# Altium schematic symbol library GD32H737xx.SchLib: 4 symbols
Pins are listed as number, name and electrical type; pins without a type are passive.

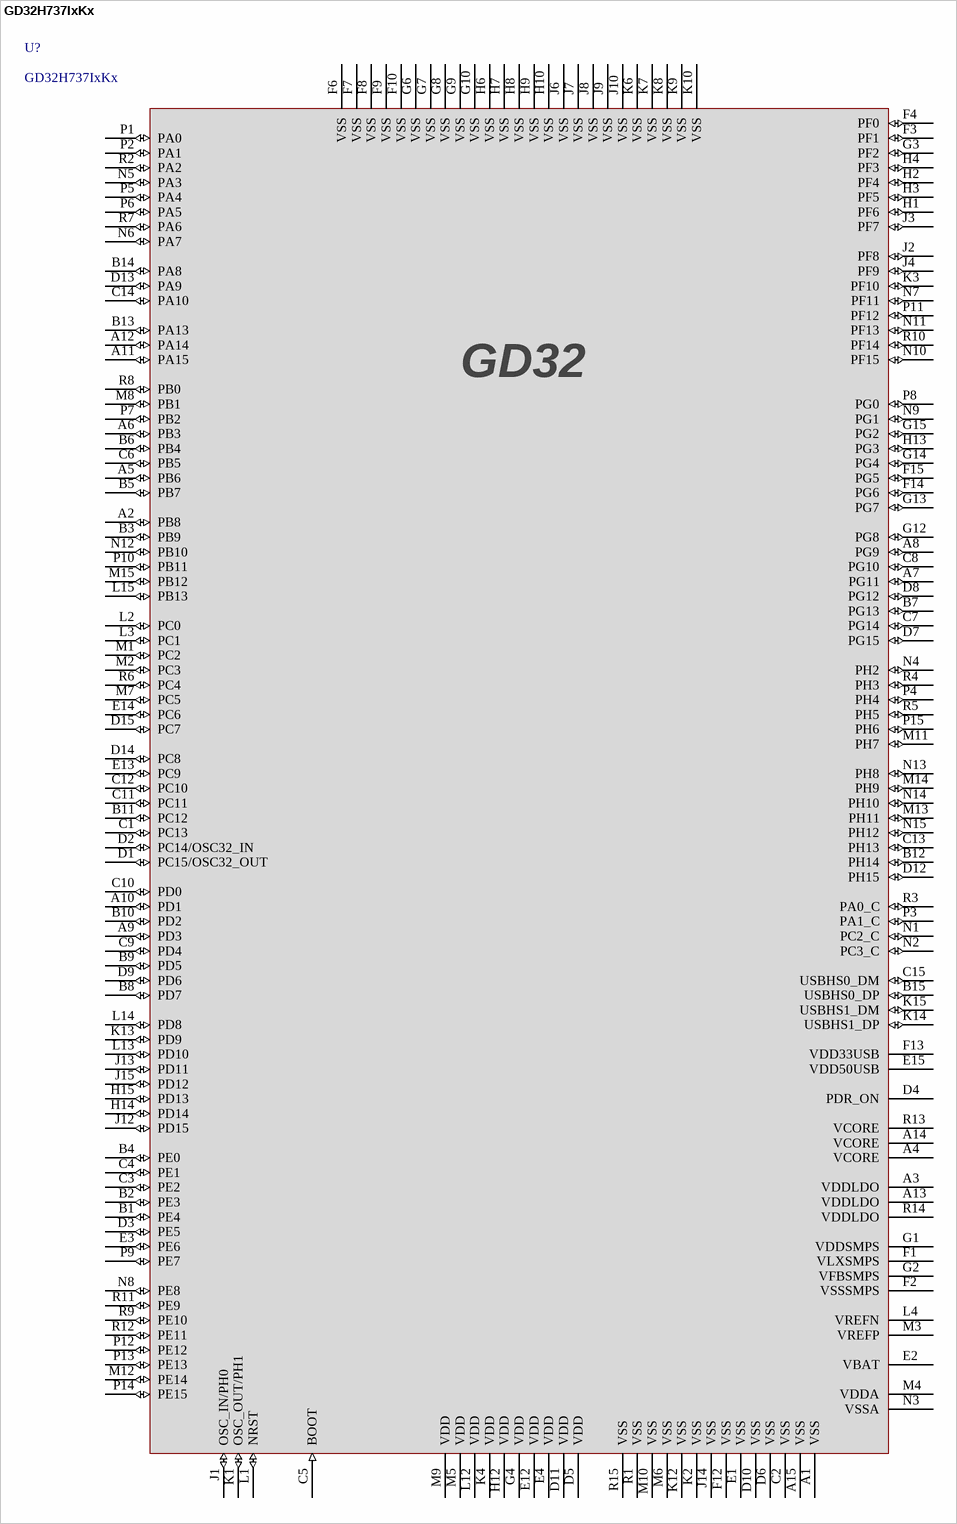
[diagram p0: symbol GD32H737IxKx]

## GD32H737IxKx
designator U?
footprint BGA176_10x10X0.68
pins: A1 VSS (power), A2 PB8 (io), A3 VDDLDO (power), A4 VCORE (power), A5 PB6 (io), A6 PB3 (io), A7 PG11 (io), A8 PG9 (io), A9 PD3 (io), A10 PD1 (io), A11 PA15 (io), A12 PA14 (io), A13 VDDLDO (power), A14 VCORE (power), A15 VSS (power), B1 PE4 (io), B2 PE3 (io), B3 PB9 (io), B4 PE0 (io), B5 PB7 (io), B6 PB4 (io), B7 PG13 (io), B8 PD7 (io), B9 PD5 (io), B10 PD2 (io), B11 PC12 (io), B12 PH14 (io), B13 PA13 (io), B14 PA8 (io), B15 USBHS0_DP (io), C1 PC13 (io), C2 VSS (power), C3 PE2 (io), C4 PE1 (io), C5 BOOT (in), C6 PB5 (io), C7 PG14 (io), C8 PG10 (io), C9 PD4 (io), C10 PD0 (io), C11 PC11 (io), C12 PC10 (io), C13 PH13 (io), C14 PA10 (io), C15 USBHS0_DM (io), D1 PC15/OSC32_OUT (io), D2 PC14/OSC32_IN (io), D3 PE5 (io), D4 PDR_ON (power), D5 VDD (power), D6 VSS (power), D7 PG15 (io), D8 PG12 (io), D9 PD6 (io), D10 VSS (power), D11 VDD (power), D12 PH15 (io), D13 PA9 (io), D14 PC8 (io), D15 PC7 (io), E1 VSS (power), E2 VBAT (power), E3 PE6 (io), E4 VDD (power), E12 VDD (power), E13 PC9 (io), E14 PC6 (io), E15 VDD50USB (power), F1 VLXSMPS (power), F2 VSSSMPS (power), F3 PF1 (io), F4 PF0 (io), F6 VSS (power), F7 VSS (power), F8 VSS (power), F9 VSS (power), F10 VSS (power), F12 VSS (power), F13 VDD33USB (power), F14 PG6 (io), F15 PG5 (io), G1 VDDSMPS (power), G2 VFBSMPS (power), G3 PF2 (io), G4 VDD (power), G6 VSS (power), G7 VSS (power), G8 VSS (power), G9 VSS (power), G10 VSS (power), G12 PG8 (io), G13 PG7 (io), G14 PG4 (io), G15 PG2 (io), H1 PF6 (io), H2 PF4 (io), H3 PF5 (io), H4 PF3 (io), H6 VSS (power), H7 VSS (power), H8 VSS (power), H9 VSS (power), H10 VSS (power), H12 VDD (power), H13 PG3 (io), H14 PD14 (io), H15 PD13 (io), J1 OSC_IN/PH0 (io), J2 PF8 (io), J3 PF7 (io), J4 PF9 (io), J6 VSS (power), J7 VSS (power), J8 VSS (power), J9 VSS (power), J10 VSS (power), J12 PD15 (io), J13 PD11 (io), J14 VSS (power), J15 PD12 (io), K1 OSC_OUT/PH1 (io), K2 VSS (power), K3 PF10 (io), K4 VDD (power), K6 VSS (power), K7 VSS (power), K8 VSS (power), K9 VSS (power), K10 VSS (power), K12 VSS (power), K13 PD9 (io), K14 USBHS1_DP (io), K15 USBHS1_DM (io), L1 NRST (io), L2 PC0 (io), L3 PC1 (io), L4 VREFN (power), L12 VDD (power), L13 PD10 (io), L14 PD8 (io), L15 PB13 (io), M1 PC2 (io), M2 PC3 (io), M3 VREFP (power), M4 VDDA (power), M5 VDD (power), M6 VSS (power), M7 PC5 (io), M8 PB1 (io), M9 VDD (power), M10 VSS (power), M11 PH7 (io), M12 PE14 (io), M13 PH11 (io), M14 PH9 (io), M15 PB12 (io), N1 PC2_C (io), N2 PC3_C (io), N3 VSSA (power), N4 PH2 (io), N5 PA3 (io), N6 PA7 (io), N7 PF11 (io), N8 PE8 (io), N9 PG1 (io), N10 PF15 (io), N11 PF13 (io), N12 PB10 (io), N13 PH8 (io), N14 PH10 (io), N15 PH12 (io), P1 PA0 (io), P2 PA1 (io), P3 PA1_C (io), P4 PH4 (io), P5 PA4 (io), P6 PA5 (io), P7 PB2 (io), P8 PG0 (io), P9 PE7 (io), P10 PB11 (io), P11 PF12 (io), P12 PE12 (io), P13 PE13 (io), P14 PE15 (io), P15 PH6 (io), R1 VSS (power), R2 PA2 (io), R3 PA0_C (io), R4 PH3 (io), R5 PH5 (io), R6 PC4 (io), R7 PA6 (io), R8 PB0 (io), R9 PE10 (io), R10 PF14 (io), R11 PE9 (io), R12 PE11 (io), R13 VCORE (power), R14 VDDLDO (power), R15 VSS (power)

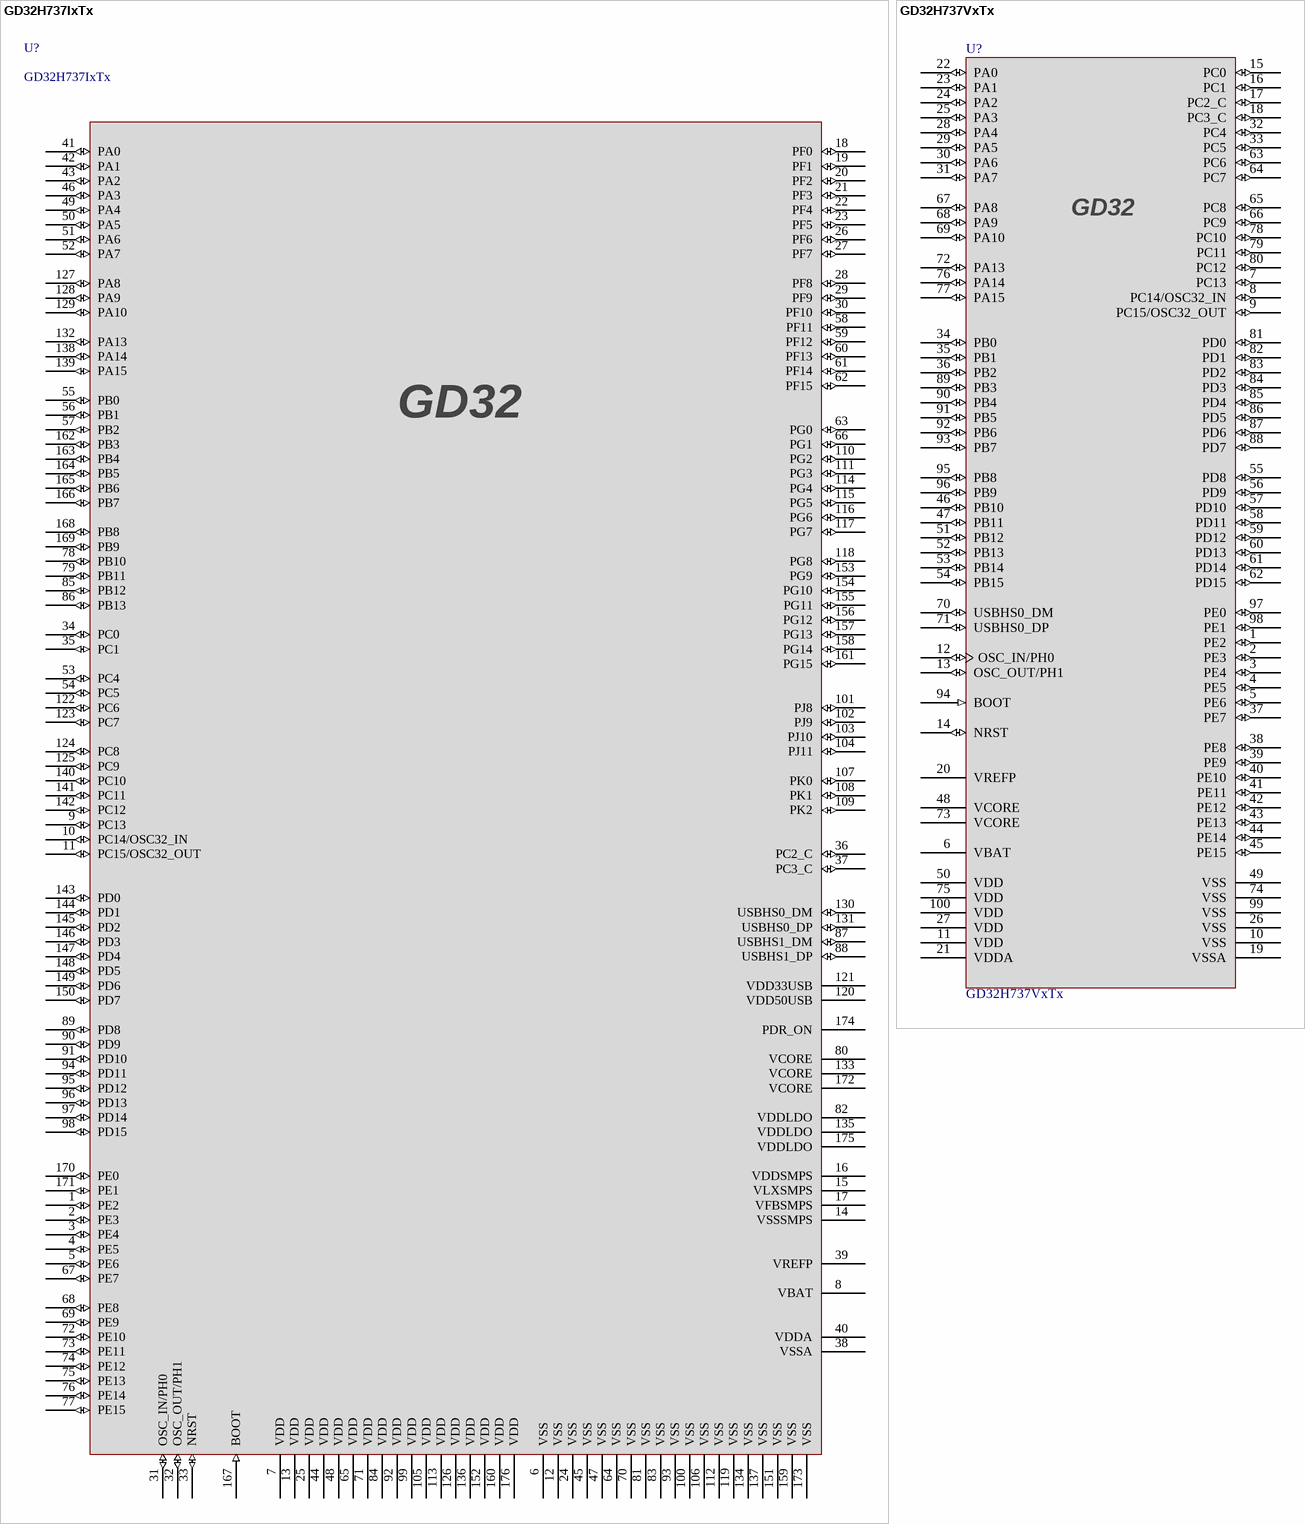
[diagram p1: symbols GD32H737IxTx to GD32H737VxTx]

## GD32H737IxTx
designator U?
footprint LQFP176_24x24X1.6
pins: 1 PE2 (io), 2 PE3 (io), 3 PE4 (io), 4 PE5 (io), 5 PE6 (io), 6 VSS (power), 7 VDD (power), 8 VBAT (power), 9 PC13 (io), 10 PC14/OSC32_IN (io), 11 PC15/OSC32_OUT (io), 12 VSS (power), 13 VDD (power), 14 VSSSMPS (power), 15 VLXSMPS (power), 16 VDDSMPS (power), 17 VFBSMPS (power), 18 PF0 (io), 19 PF1 (io), 20 PF2 (io), 21 PF3 (io), 22 PF4 (io), 23 PF5 (io), 24 VSS (power), 25 VDD (power), 26 PF6 (io), 27 PF7 (io), 28 PF8 (io), 29 PF9 (io), 30 PF10 (io), 31 OSC_IN/PH0 (io), 32 OSC_OUT/PH1 (io), 33 NRST (io), 34 PC0 (io), 35 PC1 (io), 36 PC2_C (io), 37 PC3_C (io), 38 VSSA (power), 39 VREFP (power), 40 VDDA (power), 41 PA0 (io), 42 PA1 (io), 43 PA2 (io), 44 VDD (power), 45 VSS (power), 46 PA3 (io), 47 VSS (power), 48 VDD (power), 49 PA4 (io), 50 PA5 (io), 51 PA6 (io), 52 PA7 (io), 53 PC4 (io), 54 PC5 (io), 55 PB0 (io), 56 PB1 (io), 57 PB2 (io), 58 PF11 (io), 59 PF12 (io), 60 PF13 (io), 61 PF14 (io), 62 PF15 (io), 63 PG0 (io), 64 VSS (power), 65 VDD (power), 66 PG1 (io), 67 PE7 (io), 68 PE8 (io), 69 PE9 (io), 70 VSS (power), 71 VDD (power), 72 PE10 (io), 73 PE11 (io), 74 PE12 (io), 75 PE13 (io), 76 PE14 (io), 77 PE15 (io), 78 PB10 (io), 79 PB11 (io), 80 VCORE (power), 81 VSS (power), 82 VDDLDO (power), 83 VSS (power), 84 VDD (power), 85 PB12 (io), 86 PB13 (io), 87 USBHS1_DM (io), 88 USBHS1_DP (io), 89 PD8 (io), 90 PD9 (io), 91 PD10 (io), 92 VDD (power), 93 VSS (power), 94 PD11 (io), 95 PD12 (io), 96 PD13 (io), 97 PD14 (io), 98 PD15 (io), 99 VDD (power), 100 VSS (power), 101 PJ8 (io), 102 PJ9 (io), 103 PJ10 (io), 104 PJ11 (io), 105 VDD (power), 106 VSS (power), 107 PK0 (io), 108 PK1 (io), 109 PK2 (io), 110 PG2 (io), 111 PG3 (io), 112 VSS (power), 113 VDD (power), 114 PG4 (io), 115 PG5 (io), 116 PG6 (io), 117 PG7 (io), 118 PG8 (io), 119 VSS (power), 120 VDD50USB (power), 121 VDD33USB (power), 122 PC6 (io), 123 PC7 (io), 124 PC8 (io), 125 PC9 (io), 126 VDD (power), 127 PA8 (io), 128 PA9 (io), 129 PA10 (io), 130 USBHS0_DM (io), 131 USBHS0_DP (io), 132 PA13 (io), 133 VCORE (power), 134 VSS (power), 135 VDDLDO (power), 136 VDD (power), 137 VSS (power), 138 PA14 (io), 139 PA15 (io), 140 PC10 (io), 141 PC11 (io), 142 PC12 (io), 143 PD0 (io), 144 PD1 (io), 145 PD2 (io), 146 PD3 (io), 147 PD4 (io), 148 PD5 (io), 149 PD6 (io), 150 PD7 (io), 151 VSS (power), 152 VDD (power), 153 PG9 (io), 154 PG10 (io), 155 PG11 (io), 156 PG12 (io), 157 PG13 (io), 158 PG14 (io), 159 VSS (power), 160 VDD (power), 161 PG15 (io), 162 PB3 (io), 163 PB4 (io), 164 PB5 (io), 165 PB6 (io), 166 PB7 (io), 167 BOOT (in), 168 PB8 (io), 169 PB9 (io), 170 PE0 (io), 171 PE1 (io), 172 VCORE (power), 173 VSS (power), 174 PDR_ON (power), 175 VDDLDO (power), 176 VDD (power)

## GD32H737VxTx
designator U?
footprint LQFP100_14x14x1.6
pins: 1 PE2 (io), 2 PE3 (io), 3 PE4 (io), 4 PE5 (io), 5 PE6 (io), 6 VBAT (power), 7 PC13 (io), 8 PC14/OSC32_IN (io), 9 PC15/OSC32_OUT (io), 10 VSS (power), 11 VDD (power), 12 OSC_IN/PH0 (io), 13 OSC_OUT/PH1 (io), 14 NRST (io), 15 PC0 (io), 16 PC1 (io), 17 PC2_C (io), 18 PC3_C (io), 19 VSSA (power), 20 VREFP (power), 21 VDDA (power), 22 PA0 (io), 23 PA1 (io), 24 PA2 (io), 25 PA3 (io), 26 VSS (power), 27 VDD (power), 28 PA4 (io), 29 PA5 (io), 30 PA6 (io), 31 PA7 (io), 32 PC4 (io), 33 PC5 (io), 34 PB0 (io), 35 PB1 (io), 36 PB2 (io), 37 PE7 (io), 38 PE8 (io), 39 PE9 (io), 40 PE10 (io), 41 PE11 (io), 42 PE12 (io), 43 PE13 (io), 44 PE14 (io), 45 PE15 (io), 46 PB10 (io), 47 PB11 (io), 48 VCORE (power), 49 VSS (power), 50 VDD (power), 51 PB12 (io), 52 PB13 (io), 53 PB14 (io), 54 PB15 (io), 55 PD8 (io), 56 PD9 (io), 57 PD10 (io), 58 PD11 (io), 59 PD12 (io), 60 PD13 (io), 61 PD14 (io), 62 PD15 (io), 63 PC6 (io), 64 PC7 (io), 65 PC8 (io), 66 PC9 (io), 67 PA8 (io), 68 PA9 (io), 69 PA10 (io), 70 USBHS0_DM (io), 71 USBHS0_DP (io), 72 PA13 (io), 73 VCORE (power), 74 VSS (power), 75 VDD (power), 76 PA14 (io), 77 PA15 (io), 78 PC10 (io), 79 PC11 (io), 80 PC12 (io), 81 PD0 (io), 82 PD1 (io), 83 PD2 (io), 84 PD3 (io), 85 PD4 (io), 86 PD5 (io), 87 PD6 (io), 88 PD7 (io), 89 PB3 (io), 90 PB4 (io), 91 PB5 (io), 92 PB6 (io), 93 PB7 (io), 94 BOOT (in), 95 PB8 (io), 96 PB9 (io), 97 PE0 (io), 98 PE1 (io), 99 VSS (power), 100 VDD (power)

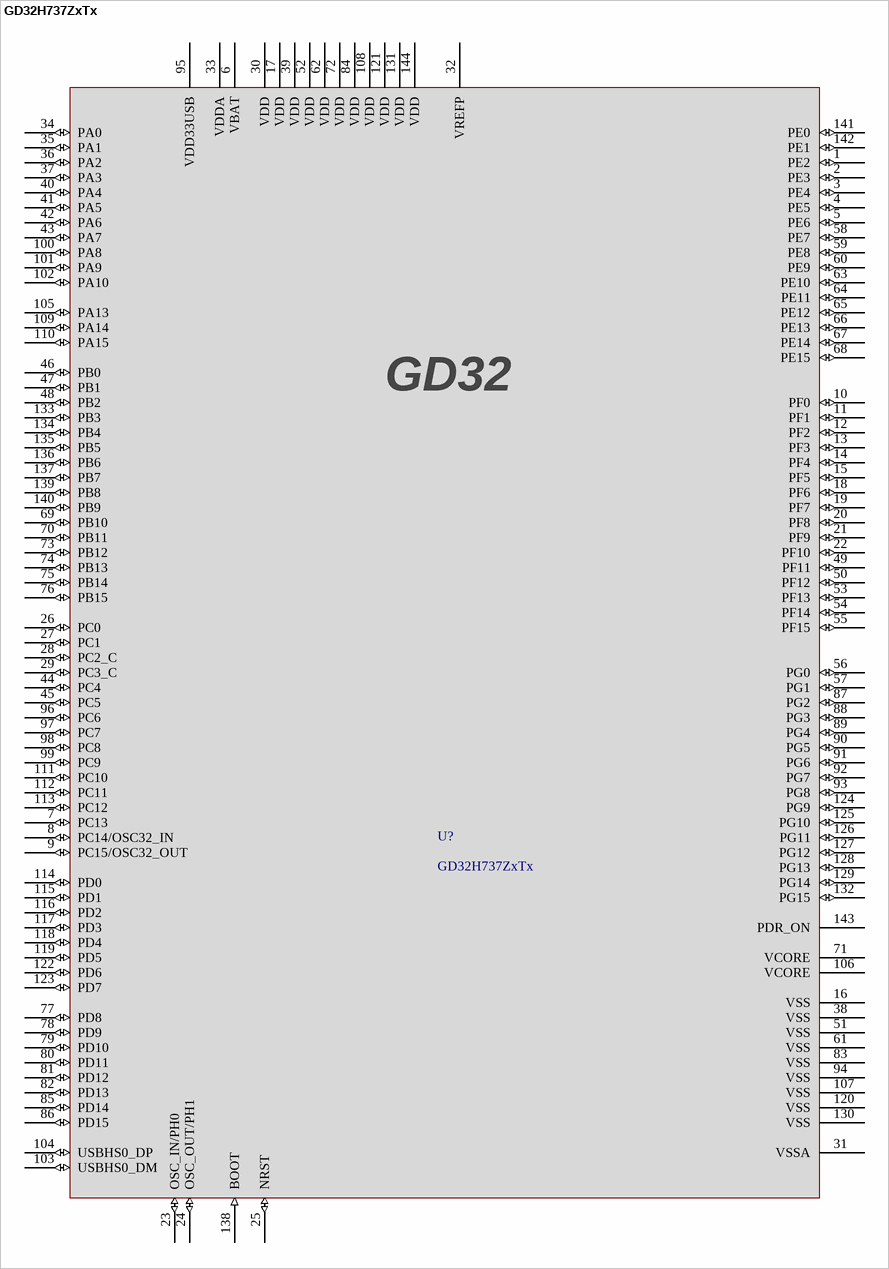
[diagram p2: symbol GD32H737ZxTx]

## GD32H737ZxTx
designator U?
footprint LQFP144_20x20X1.6
pins: 1 PE2 (io), 2 PE3 (io), 3 PE4 (io), 4 PE5 (io), 5 PE6 (io), 6 VBAT (power), 7 PC13 (io), 8 PC14/OSC32_IN (io), 9 PC15/OSC32_OUT (io), 10 PF0 (io), 11 PF1 (io), 12 PF2 (io), 13 PF3 (io), 14 PF4 (io), 15 PF5 (io), 16 VSS (power), 17 VDD (power), 18 PF6 (io), 19 PF7 (io), 20 PF8 (io), 21 PF9 (io), 22 PF10 (io), 23 OSC_IN/PH0 (io), 24 OSC_OUT/PH1 (io), 25 NRST (io), 26 PC0 (io), 27 PC1 (io), 28 PC2_C (io), 29 PC3_C (io), 30 VDD (power), 31 VSSA (power), 32 VREFP (power), 33 VDDA (power), 34 PA0 (io), 35 PA1 (io), 36 PA2 (io), 37 PA3 (io), 38 VSS (power), 39 VDD (power), 40 PA4 (io), 41 PA5 (io), 42 PA6 (io), 43 PA7 (io), 44 PC4 (io), 45 PC5 (io), 46 PB0 (io), 47 PB1 (io), 48 PB2 (io), 49 PF11 (io), 50 PF12 (io), 51 VSS (power), 52 VDD (power), 53 PF13 (io), 54 PF14 (io), 55 PF15 (io), 56 PG0 (io), 57 PG1 (io), 58 PE7 (io), 59 PE8 (io), 60 PE9 (io), 61 VSS (power), 62 VDD (power), 63 PE10 (io), 64 PE11 (io), 65 PE12 (io), 66 PE13 (io), 67 PE14 (io), 68 PE15 (io), 69 PB10 (io), 70 PB11 (io), 71 VCORE (power), 72 VDD (power), 73 PB12 (io), 74 PB13 (io), 75 PB14 (io), 76 PB15 (io), 77 PD8 (io), 78 PD9 (io), 79 PD10 (io), 80 PD11 (io), 81 PD12 (io), 82 PD13 (io), 83 VSS (power), 84 VDD (power), 85 PD14 (io), 86 PD15 (io), 87 PG2 (io), 88 PG3 (io), 89 PG4 (io), 90 PG5 (io), 91 PG6 (io), 92 PG7 (io), 93 PG8 (io), 94 VSS (power), 95 VDD33USB (power), 96 PC6 (io), 97 PC7 (io), 98 PC8 (io), 99 PC9 (io), 100 PA8 (io), 101 PA9 (io), 102 PA10 (io), 103 USBHS0_DM (io), 104 USBHS0_DP (io), 105 PA13 (io), 106 VCORE (power), 107 VSS (power), 108 VDD (power), 109 PA14 (io), 110 PA15 (io), 111 PC10 (io), 112 PC11 (io), 113 PC12 (io), 114 PD0 (io), 115 PD1 (io), 116 PD2 (io), 117 PD3 (io), 118 PD4 (io), 119 PD5 (io), 120 VSS (power), 121 VDD (power), 122 PD6 (io), 123 PD7 (io), 124 PG9 (io), 125 PG10 (io), 126 PG11 (io), 127 PG12 (io), 128 PG13 (io), 129 PG14 (io), 130 VSS (power), 131 VDD (power), 132 PG15 (io), 133 PB3 (io), 134 PB4 (io), 135 PB5 (io), 136 PB6 (io), 137 PB7 (io), 138 BOOT (in), 139 PB8 (io), 140 PB9 (io), 141 PE0 (io), 142 PE1 (io), 143 PDR_ON (power), 144 VDD (power)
